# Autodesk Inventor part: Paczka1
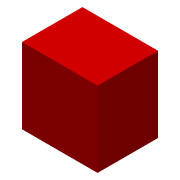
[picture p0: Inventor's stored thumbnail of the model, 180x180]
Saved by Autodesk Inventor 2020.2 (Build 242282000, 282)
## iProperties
Created: 2006-01
Part Number: Paczka1
Document SubType Name: Modeling
Designer: F.Stasiak
Stock Number: Paczka1
Density: 1 g/cm^3
Material: Ogólny
Appearance: Czerwony
Manager: www.cadconsulting.pl
Company: Fabian Stasiak CAD Consulting
Author: F.Stasiak
Subject: Zbiór ćwiczeń. Autodesk Inventor 2020. Kurs podstawowy
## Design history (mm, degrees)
sketch "Szkic1"
  geometry: L1 (-500, 400)-(500, 400); L2 (500, 400)-(500, -400); L3 (500, -400)-(-500, -400); L4 (-500, -400)-(-500, 400); L5 (0, 400)-(0, -400); 2 further points
  constraints: 10 end point, 3 midpoint, 2 parallel, 1 coincident, 1 horizontal, 1 perpendicular
  dimensions: "d0" = 800 distance of L3.end L1.start; "d1" = 1000 distance of L2.end L3.end
extrude "Wyciągnięcie proste1" new body sketch "Szkic1" distance "d2" = 1000; taper "d3" = 0 deg
node "Bryła1"
node "Korpusy bryłowe"
node "Korpusy powierzchniowe"
